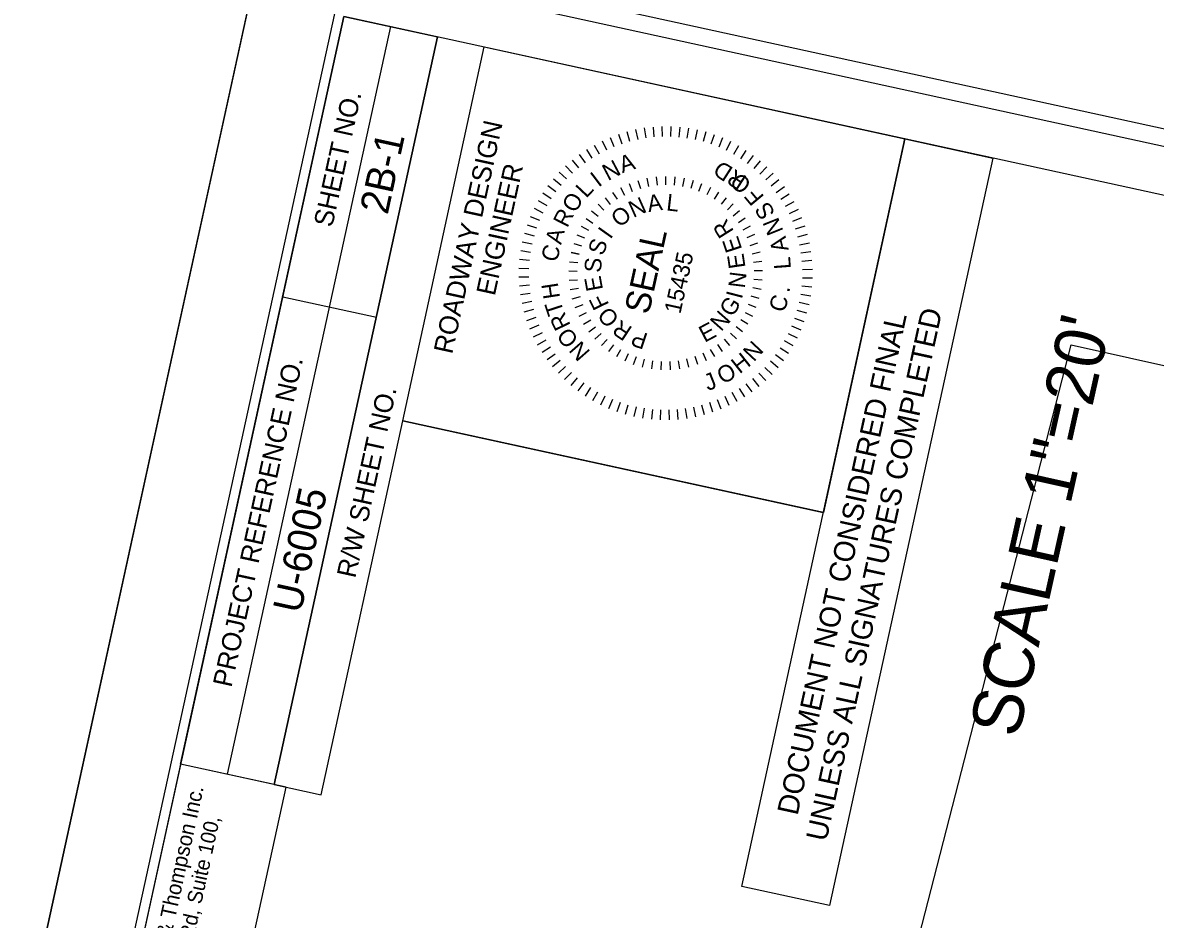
# Model space of a CAD drawing. Extents: x 1616330 to 1616903, y 901240 to 902105.
# Drawn here: x 1616448.1 to 1616566.5, y 901889.1 to 901982.9 of the extents above; entities that cross this region are included whole.
import ezdxf

# ---------------------------------------------------------------- set-up
doc = ezdxf.new("R2010")
doc.units = 0
for name, color, linetype in [('Default', 7, 'Continuous'), ('Old_Level_21', 7, 'Continuous'), ('Prop Horizontal Alignment Station Label', 7, 'Continuous'), ('Sheet Border Standard 30in CELL', 7, 'Continuous'), ('Sheet Clip Boundary CELL', 7, 'Continuous'), ('Sheet Cutting Line CELL', 7, 'Continuous'), ('Sheet Data Field CELL', 7, 'Continuous'), ('Sheet Plot Border Inside CELL', 7, 'Continuous'), ('Sheet Plot Border Outside CELL', 7, 'Continuous'), ('Sheet Sticker Exception Certification CELL', 7, 'Continuous')]:
    doc.layers.add(name, color=color, linetype=linetype)

msp = doc.modelspace()

# ---------------------------------------------------------------- linework, layer by layer
at = {"layer": 'Default'}
msp.add_lwpolyline([(1616462.33, 901841.85), (1616475.65, 901902.93), (1616464.63, 901905.33), (1616451.31, 901844.26)], close=True, dxfattribs=at)
at = {"layer": 'Old_Level_21'}
for p, q in [((1616512.18, 901971.67), (1616512.4, 901970.65)), ((1616513.09, 901971.84), (1616513.25, 901970.8)), ((1616514.01, 901971.94), (1616514.1, 901970.9)), ((1616514.94, 901972), (1616514.97, 901970.95)), ((1616515.87, 901971.99), (1616515.83, 901970.95)), ((1616516.79, 901971.93), (1616516.69, 901970.89)), ((1616517.71, 901971.81), (1616517.55, 901970.78)), ((1616518.62, 901971.64), (1616518.4, 901970.62)), ((1616508.68, 901970.48), (1616509.13, 901969.54)), ((1616509.53, 901970.86), (1616509.92, 901969.89)), ((1616510.39, 901971.18), (1616510.73, 901970.19)), ((1616511.28, 901971.46), (1616511.56, 901970.45)), ((1616519.52, 901971.42), (1616519.24, 901970.41)), ((1616520.4, 901971.14), (1616520.06, 901970.15)), ((1616521.27, 901970.8), (1616520.87, 901969.84)), ((1616522.11, 901970.42), (1616521.65, 901969.48)), ((1616507.06, 901969.58), (1616507.62, 901968.7)), ((1616507.86, 901970.06), (1616508.37, 901969.14)), ((1616522.93, 901969.98), (1616522.41, 901969.07)), ((1616523.72, 901969.5), (1616523.15, 901968.63)), ((1616505.56, 901968.49), (1616506.23, 901967.68)), ((1616506.3, 901969.06), (1616506.91, 901968.21)), ((1616524.48, 901968.97), (1616523.86, 901968.13)), ((1616525.21, 901968.4), (1616524.54, 901967.59)), ((1616504.21, 901967.23), (1616504.97, 901966.51)), ((1616504.87, 901967.88), (1616505.58, 901967.11)), ((1616525.9, 901967.78), (1616525.18, 901967.02)), ((1616526.55, 901967.12), (1616525.79, 901966.41)), ((1616503.02, 901965.81), (1616503.85, 901965.19)), ((1616503.59, 901966.54), (1616504.39, 901965.86)), ((1616511.5, 901966.02), (1616511.84, 901965.21)), ((1616512.42, 901966.34), (1616512.68, 901965.51)), ((1616513.37, 901966.58), (1616513.54, 901965.72)), ((1616514.34, 901966.72), (1616514.43, 901965.85)), ((1616515.32, 901966.77), (1616515.32, 901965.9)), ((1616516.29, 901966.72), (1616516.21, 901965.86)), ((1616517.26, 901966.58), (1616517.09, 901965.73)), ((1616518.21, 901966.35), (1616517.96, 901965.51)), ((1616518.78, 901965.23), (1616519.1, 901966.04)), ((1616527.16, 901966.42), (1616526.36, 901965.76)), ((1616527.73, 901965.69), (1616526.89, 901965.07)), ((1616502.48, 901965.05), (1616503.36, 901964.48)), ((1616508.99, 901964.53), (1616509.53, 901963.85)), ((1616509.78, 901965.11), (1616510.26, 901964.38)), ((1616510.62, 901965.6), (1616511.02, 901964.83)), ((1616520.02, 901965.62), (1616519.62, 901964.84)), ((1616520.86, 901965.12), (1616520.39, 901964.39)), ((1616521.65, 901964.55), (1616521.11, 901963.87)), ((1616528.25, 901964.92), (1616527.37, 901964.36)), ((1616501.57, 901963.44), (1616502.5, 901962.98)), ((1616502, 901964.26), (1616502.91, 901963.74)), ((1616508.26, 901963.88), (1616508.87, 901963.26)), ((1616522.38, 901963.9), (1616521.78, 901963.28)), ((1616528.73, 901964.13), (1616527.82, 901963.62)), ((1616529.16, 901963.3), (1616528.22, 901962.85)), ((1616501.18, 901962.6), (1616502.15, 901962.19)), ((1616507, 901962.39), (1616507.72, 901961.9)), ((1616507.59, 901963.17), (1616508.26, 901962.61)), ((1616523.05, 901963.19), (1616522.39, 901962.62)), ((1616523.64, 901962.41), (1616522.93, 901961.91)), ((1616529.53, 901962.46), (1616528.57, 901962.06)), ((1616500.85, 901961.73), (1616501.84, 901961.39)), ((1616506.48, 901961.56), (1616507.25, 901961.14)), ((1616524.16, 901961.58), (1616523.4, 901961.16)), ((1616529.86, 901961.59), (1616528.87, 901961.25)), ((1616500.34, 901959.95), (1616501.36, 901959.72)), ((1616500.57, 901960.85), (1616501.58, 901960.56)), ((1616505.71, 901959.77), (1616506.54, 901959.5)), ((1616506.05, 901960.68), (1616506.85, 901960.34)), ((1616524.6, 901960.71), (1616523.8, 901960.36)), ((1616524.94, 901959.79), (1616524.11, 901959.52)), ((1616530.13, 901960.7), (1616529.12, 901960.43)), ((1616530.35, 901959.8), (1616529.32, 901959.59)), ((1616500.17, 901959.04), (1616501.2, 901958.87)), ((1616505.45, 901958.83), (1616506.3, 901958.64)), ((1616506.3, 901958.64), (1616505.45, 901958.83)), ((1616525.2, 901958.85), (1616524.35, 901958.66)), ((1616530.51, 901958.89), (1616529.47, 901958.74)), ((1616500.06, 901958.12), (1616501.1, 901958.02)), ((1616505.29, 901957.86), (1616506.15, 901957.76)), ((1616525.37, 901957.89), (1616524.5, 901957.78)), ((1616530.62, 901957.97), (1616529.57, 901957.88)), ((1616499.99, 901957.19), (1616501.04, 901957.16)), ((1616499.99, 901956.27), (1616501.03, 901956.29)), ((1616505.22, 901956.89), (1616506.09, 901956.87)), ((1616525.44, 901956.91), (1616524.57, 901956.89)), ((1616530.67, 901957.04), (1616529.62, 901957.02)), ((1616500.04, 901955.34), (1616501.08, 901955.43)), ((1616505.24, 901955.91), (1616506.11, 901955.97)), ((1616505.36, 901954.94), (1616506.22, 901955.09)), ((1616525.3, 901954.96), (1616524.44, 901955.11)), ((1616525.42, 901955.93), (1616524.55, 901956)), ((1616530.6, 901955.19), (1616529.56, 901955.29)), ((1616530.66, 901956.12), (1616529.62, 901956.15)), ((1616500.15, 901954.42), (1616501.18, 901954.57)), ((1616505.57, 901953.99), (1616506.41, 901954.22)), ((1616525.09, 901954.01), (1616524.25, 901954.24)), ((1616530.49, 901954.27), (1616529.45, 901954.44)), ((1616500.31, 901953.51), (1616501.33, 901953.72)), ((1616500.53, 901952.61), (1616501.54, 901952.88)), ((1616505.88, 901953.06), (1616506.69, 901953.37)), ((1616524.79, 901953.08), (1616523.97, 901953.39)), ((1616530.09, 901952.46), (1616529.08, 901952.75)), ((1616530.32, 901953.36), (1616529.29, 901953.59)), ((1616500.8, 901951.72), (1616501.79, 901952.06)), ((1616506.27, 901952.16), (1616507.05, 901952.55)), ((1616506.75, 901951.31), (1616507.49, 901951.77)), ((1616523.93, 901951.33), (1616523.18, 901951.79)), ((1616523.62, 901952.56), (1616524.4, 901952.18)), ((1616529.81, 901951.58), (1616528.82, 901951.92)), ((1616501.12, 901950.85), (1616502.09, 901951.25)), ((1616501.5, 901950.01), (1616502.44, 901950.46)), ((1616507.3, 901950.51), (1616507.99, 901951.04)), ((1616507.93, 901949.76), (1616508.57, 901950.35)), ((1616522.74, 901949.78), (1616522.1, 901950.37)), ((1616523.37, 901950.53), (1616522.68, 901951.05)), ((1616529.09, 901949.87), (1616528.15, 901950.33)), ((1616529.48, 901950.71), (1616528.51, 901951.12)), ((1616501.93, 901949.18), (1616502.84, 901949.69)), ((1616508.63, 901949.08), (1616509.21, 901949.73)), ((1616509.39, 901948.47), (1616509.91, 901949.17)), ((1616521.28, 901948.48), (1616520.77, 901949.19)), ((1616522.04, 901949.09), (1616521.47, 901949.75)), ((1616528.66, 901949.05), (1616527.75, 901949.57)), ((1616502.4, 901948.39), (1616503.28, 901948.95)), ((1616502.93, 901947.62), (1616503.77, 901948.24)), ((1616510.21, 901947.93), (1616510.65, 901948.69)), ((1616511.08, 901947.48), (1616511.44, 901948.27)), ((1616511.98, 901947.11), (1616512.27, 901947.93)), ((1616518.7, 901947.12), (1616518.41, 901947.94)), ((1616519.6, 901947.49), (1616519.23, 901948.28)), ((1616520.47, 901947.94), (1616520.02, 901948.69)), ((1616527.64, 901947.5), (1616526.8, 901948.12)), ((1616528.17, 901948.26), (1616527.3, 901948.83)), ((1616503.49, 901946.89), (1616504.3, 901947.55)), ((1616504.11, 901946.19), (1616504.87, 901946.91)), ((1616512.92, 901946.83), (1616513.13, 901947.68)), ((1616513.88, 901946.65), (1616514, 901947.51)), ((1616514.85, 901946.55), (1616514.89, 901947.42)), ((1616515.83, 901946.55), (1616515.79, 901947.42)), ((1616516.8, 901946.65), (1616516.68, 901947.51)), ((1616517.76, 901946.84), (1616517.55, 901947.69)), ((1616526.45, 901946.08), (1616525.69, 901946.8)), ((1616527.07, 901946.77), (1616526.27, 901947.45)), ((1616504.76, 901945.53), (1616505.48, 901946.29)), ((1616505.45, 901944.92), (1616506.12, 901945.72)), ((1616525.1, 901944.82), (1616524.43, 901945.63)), ((1616525.79, 901945.43), (1616525.08, 901946.2)), ((1616506.18, 901944.34), (1616506.8, 901945.18)), ((1616506.94, 901943.81), (1616507.51, 901944.69)), ((1616523.6, 901943.73), (1616523.03, 901944.61)), ((1616524.36, 901944.25), (1616523.75, 901945.1)), ((1616507.73, 901943.33), (1616508.24, 901944.24)), ((1616508.55, 901942.89), (1616509.01, 901943.83)), ((1616509.39, 901942.51), (1616509.79, 901943.47)), ((1616510.25, 901942.18), (1616510.6, 901943.16)), ((1616521.13, 901942.45), (1616520.74, 901943.42)), ((1616521.98, 901942.83), (1616521.53, 901943.77)), ((1616522.8, 901943.25), (1616522.29, 901944.17)), ((1616511.14, 901941.9), (1616511.42, 901942.9)), ((1616512.04, 901941.67), (1616512.26, 901942.69)), ((1616512.95, 901941.5), (1616513.11, 901942.53)), ((1616513.87, 901941.38), (1616513.97, 901942.42)), ((1616514.79, 901941.32), (1616514.83, 901942.37)), ((1616515.72, 901941.32), (1616515.69, 901942.36)), ((1616516.64, 901941.37), (1616516.56, 901942.41)), ((1616517.56, 901941.47), (1616517.41, 901942.51)), ((1616518.48, 901941.64), (1616518.26, 901942.66)), ((1616519.38, 901941.85), (1616519.1, 901942.86)), ((1616520.26, 901942.13), (1616519.93, 901943.12))]:
    msp.add_line(p, q, dxfattribs=at)
at = {"layer": 'Sheet Border Standard 30in CELL'}
for p, q in [((1616469.54, 901904.26), (1616486.6, 901982.44)), ((1616474.42, 901903.2), (1616491.49, 901981.37)), ((1616474.42, 901903.2), (1616491.49, 901981.37)), ((1616475.32, 901954.2), (1616485.09, 901952.06)), ((1616479.31, 901902.13), (1616487.84, 901941.23)), ((1616487.84, 901941.23), (1616531.79, 901931.64)), ((1616474.42, 901903.2), (1616479.31, 901902.13))]:
    msp.add_line(p, q, dxfattribs=at)
for points in [[(1616481.7, 901983.51), (1616353.74, 901397.31), (1616764.08, 901307.74), (1616892.04, 901893.94)], [(1616464.63, 901905.33), (1616481.7, 901983.51), (1616491.49, 901981.37), (1616474.42, 901903.2)], [(1616487.84, 901941.23), (1616496.37, 901980.31), (1616540.34, 901970.71), (1616531.81, 901931.63)]]:
    msp.add_lwpolyline(points, close=True, dxfattribs=at)
at = {"layer": 'Sheet Clip Boundary CELL'}
msp.add_lwpolyline([(1616418.32, 901636.55), (1616453.3, 901785.32), (1616537.99, 901872.41), (1616557.7, 901949.17), (1616874.13, 901878.62), (1616760.29, 901314.11), (1616376.33, 901414.34)], close=True, dxfattribs=at)
at = {"layer": 'Sheet Cutting Line CELL'}
msp.add_line((1616473.38, 901992.29), (1616329.72, 901334.18), dxfattribs=at)
at = {"layer": 'Sheet Plot Border Inside CELL'}
msp.add_lwpolyline([(1616481.77, 901988.61), (1616339.61, 901337.35), (1616751.94, 901247.34), (1616894.1, 901898.61)], close=True, dxfattribs=at)
at = {"layer": 'Sheet Plot Border Outside CELL'}
msp.add_lwpolyline([(1616473.38, 901992.29), (1616329.72, 901334.18), (1616759.6, 901240.35), (1616903.26, 901898.45)], close=True, dxfattribs=at)
at = {"layer": 'Sheet Sticker Exception Certification CELL'}
for p, q in [((1616523.27, 901892.53), (1616540.34, 901970.71)), ((1616540.34, 901970.71), (1616549.53, 901968.7)), ((1616549.52, 901968.7), (1616532.46, 901890.53)), ((1616532.46, 901890.53), (1616523.27, 901892.53))]:
    msp.add_line(p, q, dxfattribs=at)

# ---------------------------------------------------------------- texts
at = {"layer": 'Default'}
for s, height, p in [('Johnson, Mirmiran, & Thompson Inc.', 1.5972, (1616459.62, 901868.79)), ('4700 Falls of Neuse Rd, Suite 100, ', 1.5516, (1616461.91, 901868.29))]:
    msp.add_text(s, height=height, rotation=77.6932, dxfattribs=at).set_placement(p)
at = {"layer": 'Old_Level_21'}
for s, height, rotation, p in [('N', 1.74, 27.891, (1616509.3, 901966.27)), ('A', 1.74, 18.1235, (1616510.8, 901967.11)), (' RD', 1.742, 147.2788, (1616524.45, 901966.35)), ('I', 1.74, 37.1855, (1616508.31, 901965.59)), ('O ', 1.742, 138.6061, (1616524.41, 901966.1)), ('L', 1.74, 46.7609, (1616507.02, 901964.43)), ('O', 1.74, 59.8972, (1616505.89, 901962.87)), ('N', 1.74, 24.0695, (1616511.94, 901962.42)), ('A', 1.74, 8.7733, (1616513.54, 901963.04)), ('L', 1.74, 353.477, (1616515.34, 901963.23)), ('F', 1.74, 129.8134, (1616525.7, 901964.66)), ('R', 1.74, 62.954, (1616505.03, 901961.33)), ('O', 1.74, 39.3658, (1616510.51, 901961.36)), ('S', 1.74, 120.9308, (1616526.83, 901962.93)), ('R', 1.74, 122.1713, (1616522.51, 901961.05)), ('N', 1.74, 112.0482, (1616527.66, 901961.07)), ('A', 1.74, 74.9634, (1616504.39, 901959.58)), ('I', 1.74, 54.662, (1616509.55, 901960.13)), ('SEAL', 2.615, 77.6064, (1616513.56, 901952.25)), ('S', 1.74, 69.9583, (1616508.78, 901958.4)), ('E', 1.74, 108.4002, (1616523.34, 901959.17)), ('A', 1.74, 103.2256, (1616528.2, 901959.1)), ('C', 1.74, 74.9634, (1616503.94, 901957.73)), ('15435', 1.742, 77.6064, (1616516.86, 901952.33)), ('E', 1.74, 98.4143, (1616523.68, 901957.26)), ('S', 1.74, 85.2545, (1616508.55, 901956.67)), ('L', 1.74, 94.223, (1616528.42, 901957.13)), ('E', 1.74, 100.5508, (1616508.79, 901954.95)), ('N', 1.74, 83.0222, (1616523.59, 901955.03)), ('H', 1.74, 98.674, (1616504.29, 901954.1)), ('.', 1.74, 81.4387, (1616528.25, 901954.57)), ('F', 1.74, 115.847, (1616509.45, 901953.37)), ('G', 1.74, 57.2978, (1616522.29, 901951.98)), ('I', 1.74, 75.3926, (1616523.28, 901953.88)), ('C', 1.74, 73.6963, (1616527.74, 901952.47)), ('T', 1.74, 108.106, (1616504.73, 901952.57)), ('R', 1.74, 116.267, (1616505.43, 901951.22)), ('O', 1.74, 131.1432, (1616510.57, 901951.94)), ('N', 1.74, 48.5316, (1616521.12, 901950.49)), ('R', 1.74, 146.4395, (1616511.95, 901950.93)), ('E', 1.74, 27.6765, (1616519.39, 901949.37)), ('O', 1.74, 129.3237, (1616506.31, 901949.74)), ('P', 1.74, 161.7357, (1616513.58, 901950.3)), ('N', 1.74, 131.2831, (1616507.53, 901948.44)), ('N', 1.74, 46.9286, (1616524.53, 901947.32)), ('H', 1.74, 38.256, (1616523.05, 901946.07)), ('O', 1.74, 29.6132, (1616521.31, 901944.99)), ('J', 1.74, 21.5414, (1616519.74, 901944.32))]:
    msp.add_text(s, height=height, rotation=rotation, dxfattribs=at).set_placement(p)
at = {"layer": 'Prop Horizontal Alignment Station Label'}
msp.add_text('SCALE 1"=20\'', height=5.25, rotation=77.4185, dxfattribs=at).set_placement((1616552.17, 901907.95))
at = {"layer": 'Sheet Border Standard 30in CELL'}
for s, p in [('SHEET NO.', (1616480.47, 901961.38)), ('ROADWAY DESIGN', (1616493.01, 901948.12)), ('ENGINEER', (1616497.46, 901954.21)), ('PROJECT REFERENCE NO.', (1616469.93, 901913.27)), ('R/W SHEET NO.', (1616482.88, 901924.69))]:
    msp.add_text(s, height=2, rotation=77.6862, dxfattribs=at).set_placement(p)
at = {"layer": 'Sheet Data Field CELL'}
for s, p in [('2B-1', (1616486.26, 901962.69)), ('U-6005', (1616477.18, 901920.99))]:
    msp.add_text(s, height=3, rotation=77.6862, dxfattribs=at).set_placement(p)
at = {"layer": 'Sheet Sticker Exception Certification CELL'}
for s, p in [('UNLESS ALL SIGNATURES COMPLETED', (1616532.12, 901897.15)), ('DOCUMENT NOT CONSIDERED FINAL', (1616529.11, 901899.88))]:
    msp.add_text(s, height=2.2, rotation=77.6862, dxfattribs=at).set_placement(p)

doc.saveas('drawing.dxf')
